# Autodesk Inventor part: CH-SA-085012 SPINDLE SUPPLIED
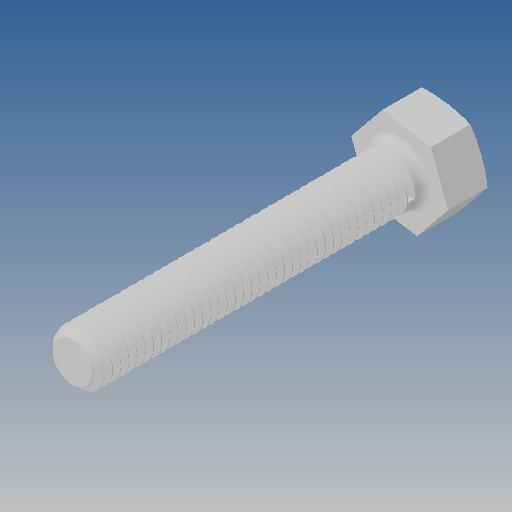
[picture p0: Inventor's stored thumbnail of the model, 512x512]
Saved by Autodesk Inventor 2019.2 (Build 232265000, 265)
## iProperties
Created: 2012-09
Part Number: CH-SA-085012 SPINDLE SUPPLIED
Material: Ogólny
Document SubType Name: Modeling
Designer: CADENGINEERING4
Density: 1 g/cm^3
Appearance: Domyślna
Author: CADENGINEERING4
Revision Number: ÈÎºÎ
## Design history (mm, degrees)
feature "ÇÐ³ý-É¨Ãè1"
node "Bryła1"
